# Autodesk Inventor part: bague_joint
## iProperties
Shininess: 64.0
Length Units: 11269
Angle Units: 11279
Time Units: 11290
Mass Units: 11283
Length Display Precision: 3
Angle Display Precision: 2
Compacted: True
Part Number: bague_joint
Document SubType Name: Modeling
Created: 2004-05
Material: Par défaut
Designer: David
Density: 0.0
Volumn: 0.0
Area: 0.0
PropertySet Name: Model Information
Control State: 0
Master: False
Checked Out: False
Author: David
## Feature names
1. Révolution1 [Revolution]
